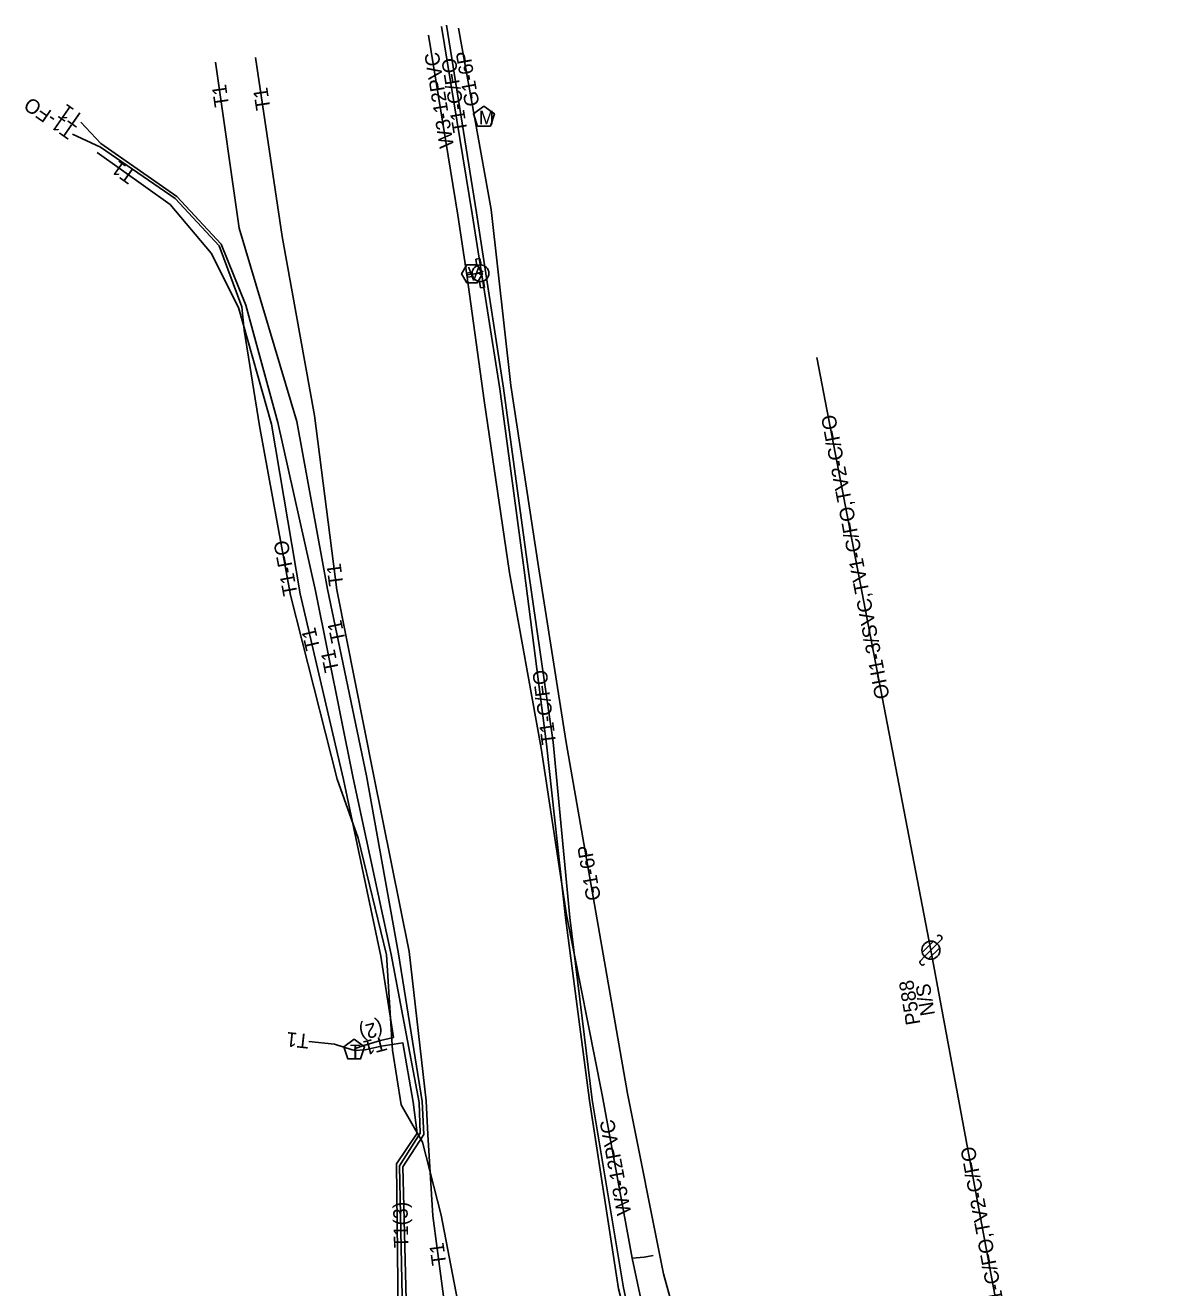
# Model space of a CAD drawing. Extents: x 2336688 to 2352634, y 362473 to 369571.
# Drawn here: x 2350273.6 to 2350587.4, y 368661.2 to 369010.3 of the extents above; entities that cross this region are included whole.
import ezdxf

# ---------------------------------------------------------------- set-up
doc = ezdxf.new("R2010")
doc.units = 0
for name, color, linetype in [('RD_EX_DV_TX_Prop', 7, 'Continuous'), ('RD_EX_RW', 7, 'Continuous'), ('RD_EX_RW_TX', 7, 'Continuous'), ('RD_HC_CL_Rel', 7, 'Continuous'), ('RD_HC_Data_Tic', 7, 'Continuous'), ('RD_PD_CstnLmt', 7, 'Continuous'), ('RD_PD_PatLn2', 7, 'Continuous'), ('RD_PD_PatLn4', 7, 'Continuous'), ('RD_SHT_ShtClip', 7, 'Continuous'), ('RD_Sketch2', 7, 'Continuous')]:
    doc.layers.add(name, color=color, linetype=linetype)

msp = doc.modelspace()

# ---------------------------------------------------------------- linework, layer by layer
at = {"layer": 'RD_EX_RW'}
for p, q in [((2350288.98, 368983.5), (2350294.55, 368977.59)), ((2350286.68, 368980.19), (2350294.43, 368976.61))]:
    msp.add_line(p, q, dxfattribs=at)
at = {"layer": 'RD_EX_RW_TX'}
for points in [[(2350388.75, 369009.97), (2350397.22, 368958.18), (2350404.87, 368909.74), (2350411.62, 368859.62), (2350417.85, 368811.58), (2350423.06, 368763.6), (2350429.71, 368713.05), (2350437.68, 368660.97), (2350447.52, 368623.27), (2350448.62, 368614.36), (2350464.25, 368567.26), (2350469.96, 368559.91), (2350480.07, 368547.98), (2350481.76, 368547.21), (2350482.64, 368545.94)], [(2350482.64, 368545.94), (2350481.31, 368546.91), (2350479.8, 368547.15), (2350468.6, 368558.68), (2350464.62, 368561.57), (2350462.94, 368566.31), (2350458.88, 368576.34), (2350449.26, 368614.59), (2350439.06, 368661.24), (2350430.47, 368713.16), (2350424.26, 368763.63), (2350419.63, 368812.07), (2350412.7, 368859.94), (2350405.88, 368909.92), (2350398.4, 368958.42), (2350390.1, 369010.31)], [(2350337.36, 369001.43), (2350344.67, 368951.86), (2350353.63, 368902.41), (2350359.81, 368854.18), (2350369.98, 368803.19), (2350379.82, 368754.22), (2350384.53, 368712.89), (2350384.98, 368703.6), (2350386.33, 368681.11), (2350389.94, 368654.04)], [(2350326.28, 369000.12), (2350332.79, 368954.21), (2350348.71, 368900.79), (2350357.27, 368854.35), (2350367.98, 368802.75), (2350376.91, 368753.55), (2350383.44, 368712.71), (2350383.88, 368703.63), (2350378.08, 368694.65), (2350379.09, 368654.23), (2350378.39, 368651.86), (2350381.3, 368648.18), (2350390.15, 368627.39), (2350394.17, 368604.93), (2350404.13, 368555.18), (2350410.09, 368526.92), (2350438.39, 368532.65), (2350479.49, 368546), (2350481.06, 368546.18), (2350482.64, 368545.94)], [(2350294.43, 368976.61), (2350315.11, 368962.45), (2350327.3, 368949.35), (2350333.57, 368932.45), (2350334.14, 368925.99), (2350338.46, 368899.59), (2350346.99, 368852.74), (2350359.86, 368801.88), (2350365.75, 368785.58), (2350373.54, 368753.3), (2350375.24, 368726.96), (2350377.57, 368711.85), (2350383.53, 368701.51), (2350388.65, 368681.34), (2350394.12, 368653.01)], [(2350408.75, 368525.77), (2350408.57, 368526.1), (2350402.78, 368554.87), (2350393.43, 368604.85), (2350388.81, 368627.14), (2350380.28, 368647.53), (2350378.39, 368651.86), (2350378.01, 368654.34), (2350377.12, 368694.93), (2350382.9, 368704.01), (2350382.6, 368712.47), (2350374.83, 368753.42), (2350364.37, 368802.15), (2350353.94, 368853.94), (2350343.54, 368900.46), (2350334.62, 368932.93), (2350327.82, 368949.81), (2350315.54, 368963), (2350294.55, 368977.59)], [(2350376.74, 368654.45), (2350376.28, 368695.46), (2350382.07, 368703.98), (2350380.88, 368712.53), (2350378.04, 368729), (2350372.12, 368728.06), (2350367.66, 368727.07), (2350364.65, 368726.82), (2350364.91, 368727.41), (2350367.3, 368728.19), (2350371.85, 368729.56), (2350375.46, 368730.48), (2350371.95, 368752.96), (2350361.66, 368801.76), (2350349.65, 368853.12), (2350341.71, 368900.04), (2350332.64, 368932.27), (2350325.09, 368947.27), (2350313.74, 368960.73), (2350293.57, 368975.16)], [(2350364.63, 368726.95), (2350364.08, 368727.07), (2350359.2, 368728.55), (2350352.09, 368729.32)]]:
    msp.add_lwpolyline(points, dxfattribs=at)
msp.add_lwpolyline([(2350364.63, 368729.95), (2350361.77, 368727.88), (2350362.86, 368724.52), (2350366.39, 368724.52), (2350367.48, 368727.88)], close=True, dxfattribs=at)
at = {"layer": 'RD_HC_CL_Rel'}
msp.add_lwpolyline([(2350393.46, 369009.48), (2350402.47, 368959.36), (2350407.9, 368910.71), (2350415.61, 368860.55), (2350423.26, 368811.96), (2350431.46, 368765.12), (2350440.2, 368714.98), (2350450.17, 368665.06), (2350463.37, 368617.29), (2350472.09, 368582.73), (2350488.34, 368552.4), (2350494.02, 368536.52), (2350510.05, 368496.62), (2350530.98, 368454.93), (2350541.05, 368432.24), (2350586.57, 368450.28), (2350584.33, 368459.13), (2350630.35, 368477.17)], dxfattribs=at)
at = {"layer": 'RD_HC_Data_Tic'}
for p, q in [((2350521.72, 368753.93), (2350524.78, 368756.99)), ((2350525.9, 368756.35), (2350526.96, 368757.41)), ((2350522.36, 368752.81), (2350525.9, 368756.35)), ((2350523.48, 368752.16), (2350526.55, 368755.23)), ((2350521.3, 368751.75), (2350522.36, 368752.81))]:
    msp.add_line(p, q, dxfattribs=at)
msp.add_circle((2350524.13, 368754.58), 2.5, dxfattribs=at)
for centre, start, end in [((2350526.43, 368757.94), 315, 135), ((2350521.83, 368751.22), 135, 315)]:
    msp.add_arc(centre, 0.75, start, end, dxfattribs=at)
at = {"layer": 'RD_SHT_ShtClip'}
for p, q in [((2350524.13, 368754.58), (2350492.59, 368918.48)), ((2350556.68, 368579.27), (2350524.13, 368754.58))]:
    msp.add_line(p, q, dxfattribs=at)
at = {"layer": 'RD_Sketch2'}
for p, q in [((2350399.41, 368945.83), (2350398.27, 368945.66)), ((2350398.27, 368945.66), (2350398.56, 368943.82)), ((2350399.69, 368944.04), (2350399.41, 368945.83)), ((2350397.26, 368942.01), (2350395.78, 368941.78)), ((2350395.78, 368941.78), (2350395.95, 368940.64)), ((2350395.95, 368940.64), (2350397.41, 368940.87)), ((2350399.23, 368939.44), (2350399.51, 368937.67)), ((2350400.65, 368937.84), (2350400.38, 368939.58)), ((2350399.51, 368937.67), (2350400.65, 368937.84))]:
    msp.add_line(p, q, dxfattribs=at)
for points in [[(2350508, 368452.18), (2350507.59, 368453.47), (2350504.92, 368459.98), (2350493.07, 368492.16), (2350477.05, 368538.83), (2350463.38, 368580.99), (2350454.69, 368615.46), (2350447.11, 368643.06), (2350441.53, 368669.46), (2350433.16, 368714.57), (2350423.37, 368764.37), (2350416.37, 368810.41), (2350407.58, 368858.95), (2350400.55, 368906.55), (2350395.74, 368941.34), (2350393.27, 368957.78), (2350385.2, 369007.61)], [(2350400.32, 368942.3), (2350398.66, 368941.66), (2350395.74, 368941.34)], [(2350441.53, 368669.46), (2350444.79, 368669.73), (2350447.27, 368670.14)]]:
    msp.add_lwpolyline(points, dxfattribs=at)
for points in [[(2350400.48, 368987.94), (2350397.58, 368985.83), (2350398.69, 368982.42), (2350402.27, 368982.42), (2350403.38, 368985.83)], [(2350400.09, 368941.6), (2350398.65, 368944.1), (2350395.76, 368944.1), (2350394.32, 368941.6), (2350395.76, 368939.1), (2350398.65, 368939.1)]]:
    msp.add_lwpolyline(points, close=True, dxfattribs=at)
for radius in [2.31, 0.289]:
    msp.add_circle((2350399.55, 368941.73), radius, dxfattribs=at)
for start, end in [(173.0252, 201.9924), (86.4646, 115.4409), (262.1183, 291.0947)]:
    msp.add_arc((2350399.55, 368941.73), 2.31, start, end, dxfattribs=at)

# ---------------------------------------------------------------- texts
at = {"layer": 'RD_EX_DV_TX_Prop'}
for s, p in [('P588', (2350521.23, 368734.23)), ('N/S', (2350525.27, 368736.76))]:
    msp.add_text(s, height=4, rotation=99.4837, dxfattribs=at).set_placement(p)
at = {"layer": 'RD_EX_RW'}
for s, rotation, p in [('T1-C/FO', 99.2882, (2350395.99, 368980.98)), ('T1', 98.0712, (2350330.02, 368987.99)), ('T1', 98.3869, (2350341.48, 368987.14)), ('T1-FO', 145.1954, (2350287.79, 368981.85)), ('T1', 145.1954, (2350290.09, 368985.17)), ('T1', 144.4339, (2350304.49, 368969.43)), ('T1-FO', 100.3146, (2350348.98, 368852.95)), ('T1', 97.2946, (2350361.65, 368855.53)), ('T1', 103.157, (2350355.23, 368838.01)), ('T1', 101.724, (2350362.28, 368840.03)), ('T1', 101.3788, (2350360.43, 368831.83)), ('T1-C/FO', 97.3937, (2350420.5, 368811.67)), ('(2)', 194.3982, (2350372, 368735.09)), ('T1', 173.8085, (2350352.3, 368731.31)), ('T1', 194.3982, (2350372.9, 368730.9)), ('T1(3)', 91.2619, (2350379.62, 368672.27)), ('T1', 97.606, (2350390.14, 368667.71))]:
    msp.add_text(s, height=4, rotation=rotation, dxfattribs=at).set_placement(p)
at = {"layer": 'RD_EX_RW_TX'}
msp.add_text('T', height=3.75, dxfattribs=at).set_placement((2350363.4, 368724.72))
at = {"layer": 'RD_PD_CstnLmt'}
for rotation, p in [(99.2, (2350392.23, 368976.69)), (100.5119, (2350441.29, 368681.72))]:
    msp.add_text('W3-12PVC', height=4, rotation=rotation, dxfattribs=at).set_placement(p)
at = {"layer": 'RD_PD_PatLn2'}
for rotation, p in [(100.2008, (2350399.31, 368988.25)), (99.9328, (2350432.88, 368768.64))]:
    msp.add_text('G1-6P', height=4, rotation=rotation, dxfattribs=at).set_placement(p)
at = {"layer": 'RD_PD_PatLn4'}
for s, rotation, p in [('OH1-3/SVC,TV1-C/FO,TV2-C/FO', 100.8925, (2350512.73, 368824.41)), ('OH1-3,TV1-C/FO,TV2-C/FO', 100.5193, (2350548.51, 368634.24))]:
    msp.add_text(s, height=4, rotation=rotation, dxfattribs=at).set_placement(p)
at = {"layer": 'RD_Sketch2'}
for s, p in [('M', (2350399.11, 368982.9)), ('V', (2350395.99, 368939.72))]:
    msp.add_text(s, height=3.75, dxfattribs=at).set_placement(p)

doc.saveas('drawing.dxf')
